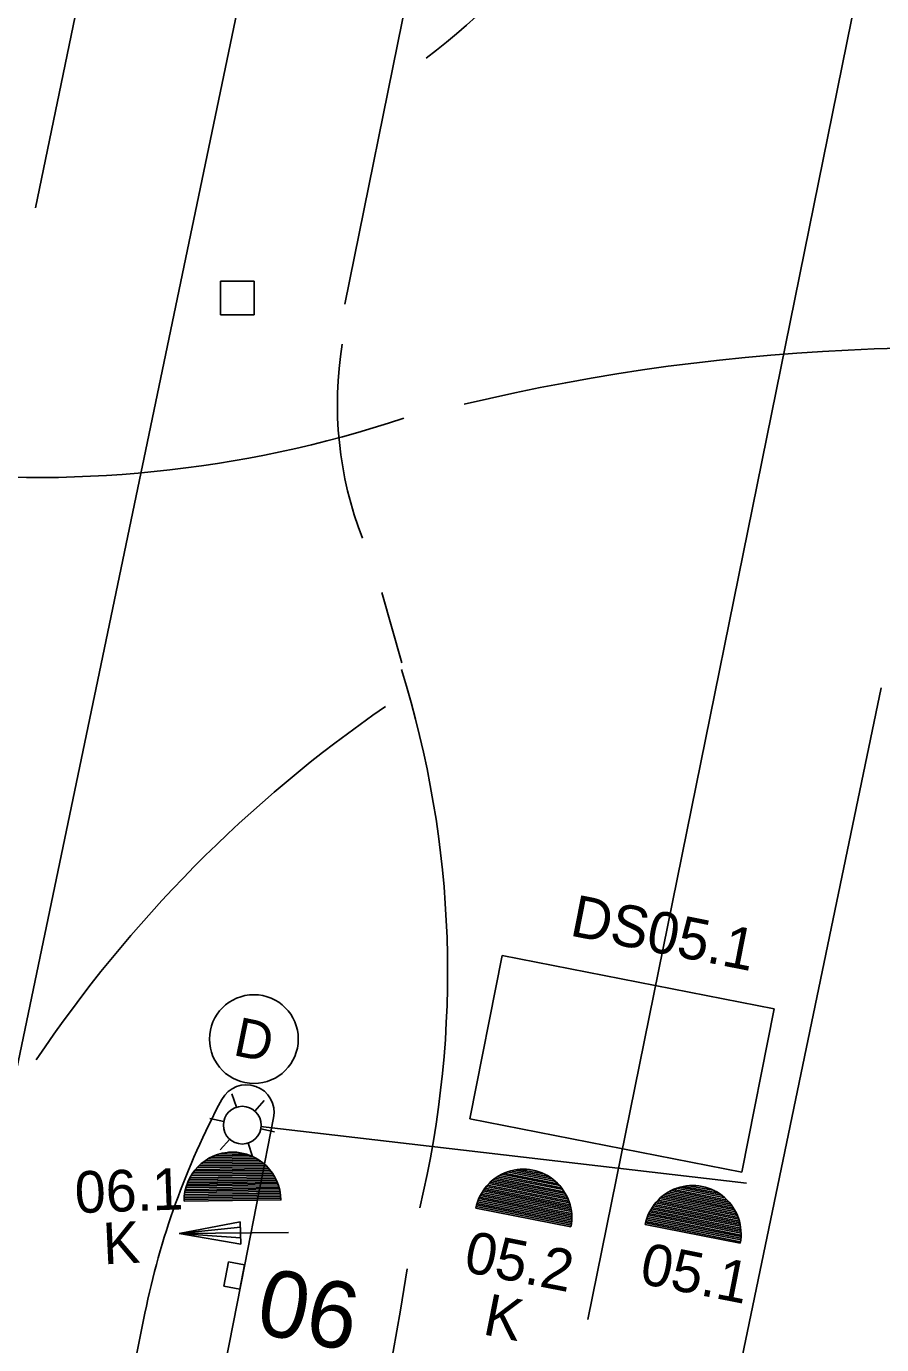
# Model space of a CAD drawing. Extents: x 81065 to 81486, y 452384 to 452681.
# Drawn here: x 81217.72 to 81233.14, y 452511.24 to 452535 of the extents above; entities that cross this region are included whole.
import ezdxf

# ---------------------------------------------------------------- set-up
doc = ezdxf.new("R2010")
doc.units = 0
for name, color, linetype in [('B-BH-RI-GWA_RIOOLPUT-S', 7, 'Continuous'), ('B-BH-VH-KANTOPSLUITING-GV', 7, 'Continuous'), ('B-SRI-KOLK_COMBINATIE-S', 7, 'Continuous'), ('B-WE-VW-MARKERING_LANGS_STREEP_11_010-G', 7, 'Continuous'), ('B-WE-VW-MARKERING_LANGS_STREEP_13_010-G', 7, 'Continuous'), ('B-WE-VW-MARKERING_LANGS_STREEP_DOORGETROKKEN_010-G', 7, 'Continuous'), ('Default', 7, 'Continuous'), ('N-OI-KL-VRI_LUS_DETECTIE_SELECTIEF-G', 7, 'Continuous'), ('N-OI-KL-VRI_LUS_DETECTIE_SELECTIEF-T18', 7, 'Continuous'), ('N-WE-VW-VRI_ARMATUUR-S', 7, 'Continuous'), ('N-WE-VW-VRI_ARMATUUR-T18', 7, 'Continuous'), ('N-WE-VW-VRI_LIGGER-G', 7, 'Continuous'), ('N-WE-VW-VRI_MAST-S', 7, 'Continuous'), ('N-WE-VW-VRI_RICHTINGNUMMER-T25', 7, 'Continuous')]:
    doc.layers.add(name, color=color, linetype=linetype)

# ---------------------------------------------------------------- blocks, each defined once
blk = doc.blocks.new('N-SVW-VRI_ARMATUUR_DOMECAMERA-SO')
at = {"layer": 'Default'}
blk.add_circle((-0.023, 0.008), 0.8, dxfattribs=at)
blk.add_text('D', height=0.7, rotation=0.0343, dxfattribs=at).set_placement((-0.353, -0.35))

msp = doc.modelspace()

# ---------------------------------------------------------------- linework, layer by layer
at = {"layer": 'B-BH-RI-GWA_RIOOLPUT-S'}
for p, q in [((81221.826, 452530.408), (81221.219, 452530.408)), ((81221.219, 452530.408), (81221.219, 452529.801)), ((81221.826, 452529.801), (81221.826, 452530.408)), ((81221.219, 452529.801), (81221.826, 452529.801))]:
    msp.add_line(p, q, dxfattribs=at)
at = {"layer": 'B-BH-VH-KANTOPSLUITING-GV'}
msp.add_line((81221.657, 452512.681), (81222.178, 452515.327), dxfattribs=at)
for points in [[(81216.352, 452496.426), (81216.569, 452496.755), (81218.27, 452500.065), (81219.607, 452503.538), (81220.564, 452507.135), (81220.599, 452507.305), (81221.657, 452512.681)], [(81219.858, 452511.805), (81219.677, 452510.904)]]:
    msp.add_lwpolyline(points, dxfattribs=at)
for centre, radius, start, end in [((81242.762, 452507.028), 9.811, 80.0525, 169.5766), ((81221.687, 452515.424), 0.5, 348.8664, 151.7783), ((81233.582, 452509.04), 14, 151.7783, 168.61)]:
    msp.add_arc(centre, radius, start, end, dxfattribs=at)
at = {"layer": 'B-SRI-KOLK_COMBINATIE-S'}
for p, q in [((81221.365, 452512.734), (81221.28, 452512.294)), ((81221.655, 452512.677), (81221.365, 452512.734)), ((81221.57, 452512.238), (81221.655, 452512.677)), ((81221.28, 452512.294), (81221.57, 452512.238))]:
    msp.add_line(p, q, dxfattribs=at)
at = {"layer": 'B-WE-VW-MARKERING_LANGS_STREEP_11_010-G'}
for p, q in [((81223.459, 452529.995), (81226.459, 452544.722)), ((81217.884, 452531.728), (81220.537, 452544.499)), ((81224.127, 452524.798), (81224.49, 452523.526)), ((81230.53, 452510.556), (81233.127, 452523.076))]:
    msp.add_line(p, q, dxfattribs=at)
for centre, radius, start, end in [((81214.36, 452547.994), 17.2, 307.9185, 332.8561), ((81230.042, 452528.193), 6.715, 170.7326, 201.0985), ((81234.269, 452491.876), 37.331, 80.4782, 103.4068), ((81217.907, 452547.865), 20.997, 263.1957, 288.3707), ((81207.065, 452517.958), 18.249, 346.5183, 17.3688), ((81237.817, 452502.981), 24.002, 124.5743, 146.087)]:
    msp.add_arc(centre, radius, start, end, dxfattribs=at)
at = {"layer": 'B-WE-VW-MARKERING_LANGS_STREEP_13_010-G'}
for p, q in [((81223.344, 452544.01), (81216.529, 452511.342)), ((81233.846, 452541.285), (81227.841, 452511.692))]:
    msp.add_line(p, q, dxfattribs=at)
at = {"layer": 'B-WE-VW-MARKERING_LANGS_STREEP_DOORGETROKKEN_010-G'}
msp.add_arc((81143.756, 452525.514), 81.855, 342.45729, 350.92873, dxfattribs=at)
at = {"layer": 'N-OI-KL-VRI_LUS_DETECTIE_SELECTIEF-G'}
for p, q in [((81226.299, 452518.256), (81225.716, 452515.312)), ((81231.202, 452517.291), (81226.299, 452518.256)), ((81230.62, 452514.345), (81231.202, 452517.291)), ((81225.716, 452515.312), (81230.62, 452514.345))]:
    msp.add_line(p, q, dxfattribs=at)
at = {"layer": 'N-WE-VW-VRI_ARMATUUR-S'}
for p, q in [((81221.364, 452514.708), (81221.493, 452514.71)), ((81220.827, 452514.46), (81222.036, 452514.476)), ((81220.858, 452514.49), (81222.001, 452514.503)), ((81220.895, 452514.523), (81221.964, 452514.535)), ((81220.935, 452514.551), (81221.924, 452514.562)), ((81220.985, 452514.581), (81221.874, 452514.592)), ((81221.036, 452514.612), (81221.819, 452514.623)), ((81221.104, 452514.643), (81221.753, 452514.652)), ((81221.192, 452514.674), (81221.665, 452514.681)), ((81220.653, 452514.218), (81222.214, 452514.236)), ((81220.668, 452514.248), (81222.197, 452514.265)), ((81220.685, 452514.279), (81222.182, 452514.295)), ((81220.703, 452514.309), (81222.162, 452514.325)), ((81220.723, 452514.339), (81222.14, 452514.355)), ((81220.745, 452514.371), (81222.118, 452514.385)), ((81220.769, 452514.399), (81222.092, 452514.414)), ((81220.797, 452514.43), (81222.066, 452514.444)), ((81226.141, 452514.216), (81227.439, 452513.961)), ((81226.173, 452514.241), (81227.418, 452513.996)), ((81226.21, 452514.264), (81227.396, 452514.033)), ((81226.247, 452514.287), (81227.368, 452514.067)), ((81226.289, 452514.312), (81227.337, 452514.105)), ((81226.335, 452514.331), (81227.304, 452514.14)), ((81226.388, 452514.353), (81227.263, 452514.181)), ((81226.447, 452514.37), (81227.215, 452514.221)), ((81226.517, 452514.387), (81227.154, 452514.264)), ((81226.611, 452514.399), (81227.075, 452514.31)), ((81226.786, 452514.395), (81226.913, 452514.372)), ((81220.576, 452513.979), (81222.296, 452513.997)), ((81220.581, 452514.009), (81222.29, 452514.028)), ((81220.587, 452514.037), (81222.282, 452514.058)), ((81220.595, 452514.069), (81222.274, 452514.086)), ((81220.604, 452514.1), (81222.265, 452514.118)), ((81220.613, 452514.127), (81222.251, 452514.148)), ((81220.625, 452514.158), (81222.241, 452514.176)), ((81220.638, 452514.188), (81222.229, 452514.206)), ((81225.933, 452513.984), (81227.543, 452513.667)), ((81225.95, 452514.009), (81227.537, 452513.697)), ((81225.969, 452514.036), (81227.531, 452513.728)), ((81225.989, 452514.062), (81227.522, 452513.761)), ((81226.01, 452514.089), (81227.511, 452513.794)), ((81226.033, 452514.115), (81227.502, 452513.826)), ((81226.057, 452514.141), (81227.489, 452513.859)), ((81226.083, 452514.167), (81227.475, 452513.893)), ((81226.112, 452514.192), (81227.458, 452513.927)), ((81229.299, 452513.992), (81230.42, 452513.771)), ((81229.341, 452514.016), (81230.389, 452513.81)), ((81229.387, 452514.036), (81230.356, 452513.845)), ((81229.44, 452514.058), (81230.316, 452513.886)), ((81229.499, 452514.075), (81230.267, 452513.926)), ((81229.569, 452514.092), (81230.206, 452513.968)), ((81229.663, 452514.104), (81230.127, 452514.015)), ((81229.838, 452514.1), (81229.965, 452514.077)), ((81220.564, 452513.827), (81222.313, 452513.847)), ((81220.565, 452513.857), (81222.31, 452513.879)), ((81220.567, 452513.887), (81222.307, 452513.909)), ((81220.569, 452513.917), (81222.306, 452513.939)), ((81220.572, 452513.947), (81222.301, 452513.969)), ((81225.837, 452513.757), (81227.547, 452513.422)), ((81225.846, 452513.785), (81227.55, 452513.452)), ((81225.855, 452513.814), (81227.553, 452513.482)), ((81225.866, 452513.844), (81227.553, 452513.51)), ((81225.877, 452513.871), (81227.554, 452513.543)), ((81225.889, 452513.899), (81227.553, 452513.574)), ((81225.904, 452513.929), (81227.55, 452513.603)), ((81225.918, 452513.954), (81227.547, 452513.636)), ((81229.021, 452513.741), (81230.583, 452513.433)), ((81229.042, 452513.767), (81230.574, 452513.466)), ((81229.062, 452513.794), (81230.563, 452513.499)), ((81229.085, 452513.82), (81230.555, 452513.531)), ((81229.109, 452513.846), (81230.542, 452513.564)), ((81229.136, 452513.871), (81230.527, 452513.598)), ((81229.164, 452513.896), (81230.51, 452513.631)), ((81229.193, 452513.921), (81230.491, 452513.666)), ((81229.226, 452513.945), (81230.471, 452513.7)), ((81229.262, 452513.969), (81230.448, 452513.737)), ((81225.823, 452513.698), (81227.537, 452513.361)), ((81225.831, 452513.727), (81227.542, 452513.39)), ((81228.907, 452513.519), (81230.605, 452513.187)), ((81228.918, 452513.549), (81230.606, 452513.215)), ((81228.93, 452513.576), (81230.606, 452513.248)), ((81228.941, 452513.604), (81230.605, 452513.279)), ((81228.956, 452513.634), (81230.602, 452513.308)), ((81228.97, 452513.659), (81230.6, 452513.341)), ((81228.986, 452513.689), (81230.596, 452513.372)), ((81229.003, 452513.714), (81230.589, 452513.402)), ((81220.475, 452513.24), (81221.577, 452513.453)), ((81221.579, 452513.354), (81220.475, 452513.24)), ((81222.446, 452513.262), (81220.475, 452513.24)), ((81221.577, 452513.453), (81221.585, 452513.051)), ((81228.876, 452513.403), (81230.589, 452513.066)), ((81228.883, 452513.432), (81230.594, 452513.095)), ((81228.889, 452513.461), (81230.599, 452513.127)), ((81228.898, 452513.49), (81230.602, 452513.157)), ((81221.585, 452513.051), (81220.475, 452513.24)), ((81221.583, 452513.165), (81220.475, 452513.24))]:
    msp.add_line(p, q, dxfattribs=at)
for centre, start, end in [((81221.437, 452513.836), 0.6407, 180.6407), ((81226.68, 452513.529), 348.8664, 168.8664), ((81229.732, 452513.234), 348.8664, 168.8664)]:
    msp.add_arc(centre, 0.873, start, end, dxfattribs=at)
at = {"layer": 'N-WE-VW-VRI_LIGGER-G'}
msp.add_line((81230.701, 452514.151), (81221.941, 452515.173), dxfattribs=at)
at = {"layer": 'N-WE-VW-VRI_MAST-S'}
for p, q in [((81221.506, 452515.518), (81221.425, 452515.76)), ((81221.838, 452515.449), (81222.008, 452515.64)), ((81221.28, 452515.264), (81221.03, 452515.315)), ((81221.387, 452514.941), (81221.217, 452514.75)), ((81221.946, 452515.127), (81222.196, 452515.075)), ((81221.72, 452514.872), (81221.8, 452514.63))]:
    msp.add_line(p, q, dxfattribs=at)
msp.add_circle((81221.613, 452515.195), 0.34, dxfattribs=at)

# ---------------------------------------------------------------- block references
at = {"layer": 'N-WE-VW-VRI_ARMATUUR-S', "rotation": -11.53193586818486}
msp.add_blockref('N-SVW-VRI_ARMATUUR_DOMECAMERA-SO', (81221.843, 452516.734), dxfattribs=at)

# ---------------------------------------------------------------- texts
at = {"layer": 'N-OI-KL-VRI_LUS_DETECTIE_SELECTIEF-T18'}
msp.add_text('DS05.1', height=0.75, rotation=348.8664, dxfattribs=at).set_placement((81227.497, 452518.617))
at = {"layer": 'N-WE-VW-VRI_ARMATUUR-S'}
for rotation, p in [(2.7542, (81219.116, 452512.685)), (348.8664, (81225.927, 452511.429))]:
    msp.add_text('K', height=0.75, rotation=rotation, dxfattribs=at).set_placement(p)
at = {"layer": 'N-WE-VW-VRI_ARMATUUR-T18'}
for s, rotation, p in [('06.1', 2.0267, (81218.606, 452513.609)), ('05.2', 348.8664, (81225.581, 452512.561)), ('05.1', 348.8664, (81228.751, 452512.349))]:
    msp.add_text(s, height=0.75, rotation=rotation, dxfattribs=at).set_placement(p)
at = {"layer": 'N-WE-VW-VRI_RICHTINGNUMMER-T25'}
msp.add_text('06', height=1.2, rotation=348.8664, dxfattribs=at).set_placement((81221.818, 452511.459))

doc.saveas('drawing.dxf')
